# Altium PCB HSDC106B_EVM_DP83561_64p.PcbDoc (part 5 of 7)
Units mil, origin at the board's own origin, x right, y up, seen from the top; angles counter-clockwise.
Board outline 8750.24 x 6394.7 mil, 6 copper layers (Top Layer, GND1, SIG1, SIG2, GND2, Bottom Layer), stack 60.4 mil thick; 472 components, 324 nets, 1622 pads, 1086 vias.
Unrouted connection lines stored in the file: 1.
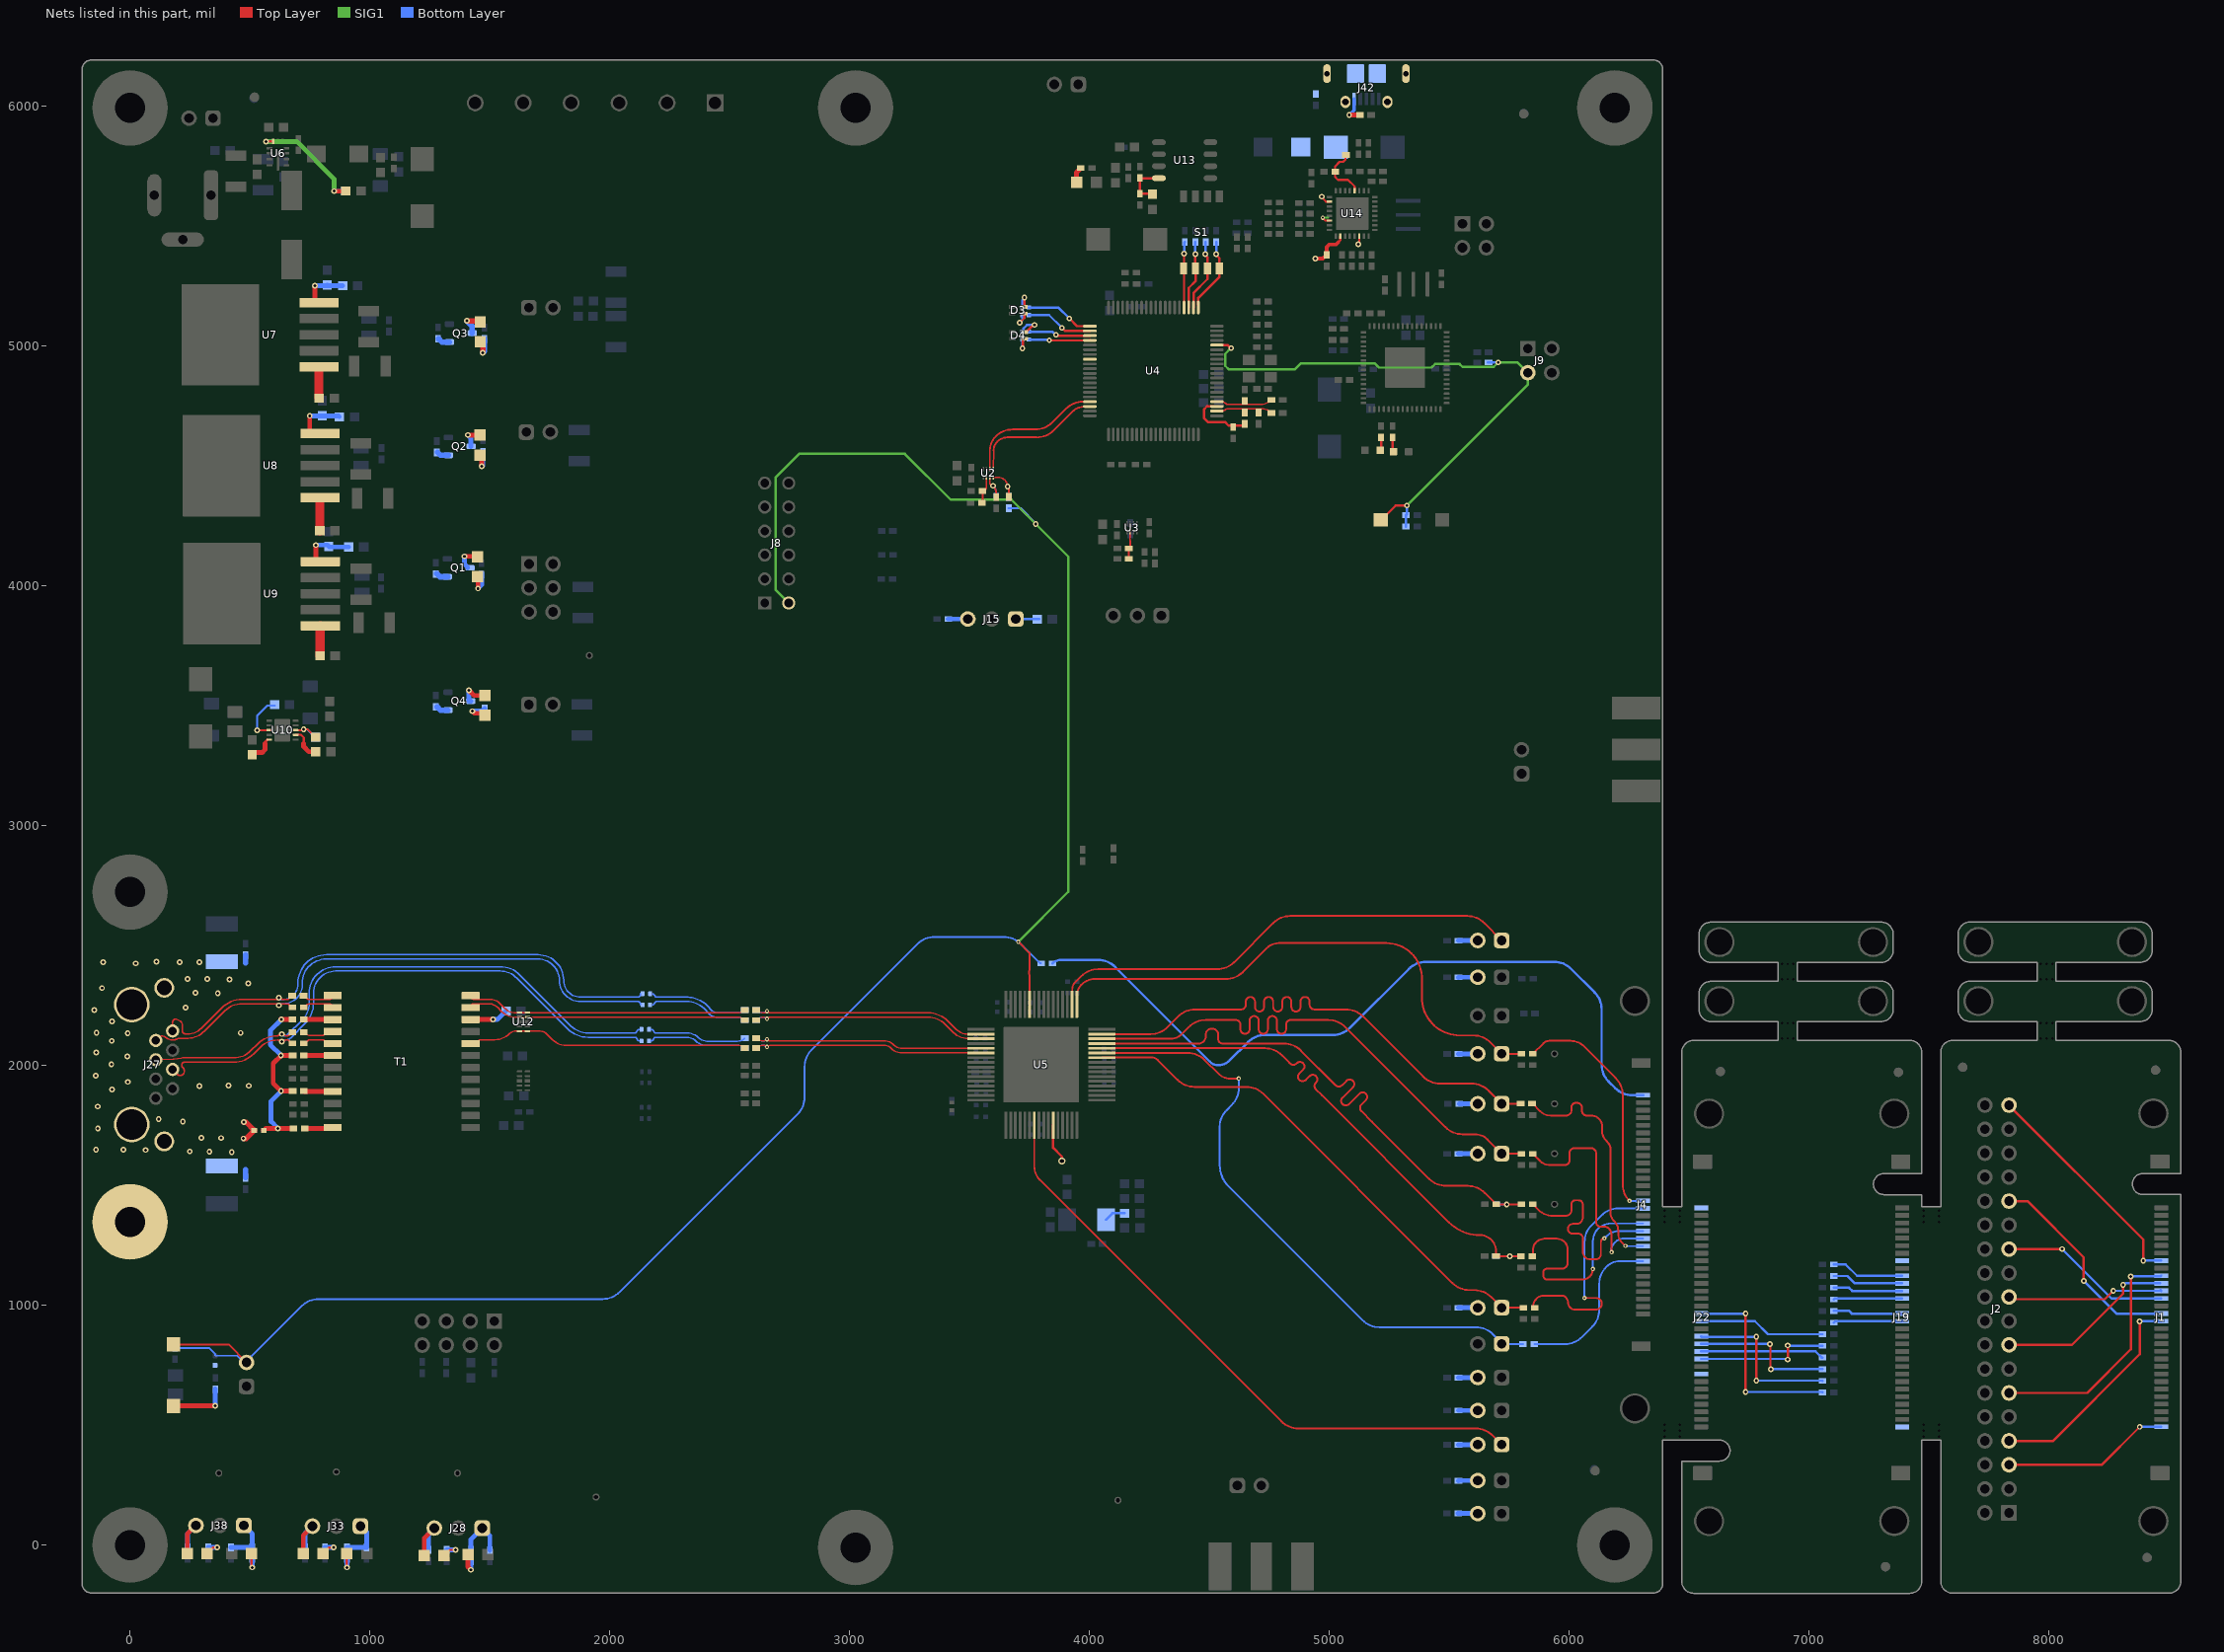
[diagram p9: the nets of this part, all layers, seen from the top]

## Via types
v1: diameter 24, hole 12, Top Layer to Bottom Layer, tented both sides, 903 vias
v2: diameter 24, hole 12, Top Layer to Bottom Layer, 65 vias
v3: diameter 18, hole 7.87, Top Layer to Bottom Layer, tented both sides, 53 vias
v4: diameter 22, hole 10, Top Layer to Bottom Layer, tented both sides, 43 vias
v5: diameter 19.68, hole 7.87, Top Layer to Bottom Layer, 21 vias
v6: diameter 22, hole 12, Top Layer to Bottom Layer, tented both sides, 1 vias

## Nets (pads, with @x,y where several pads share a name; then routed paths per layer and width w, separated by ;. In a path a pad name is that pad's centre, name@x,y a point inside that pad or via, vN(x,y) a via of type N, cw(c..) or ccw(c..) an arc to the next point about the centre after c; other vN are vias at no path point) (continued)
NetC79_2: C79.2 T1.10 | length 162.7
  Top Layer w20: T1.10@1419.86,2191.7 v1(1513.87,2191.7)
  Bottom Layer w20: v1(1513.87,2191.7) 1531.2,2191.7 C79.2@1567.5,2228
NetC82_1: C82.1 R107.1 R114.1 R117.1 R123.1 | length 819.7
  Top Layer w20: C82.1@557.28,1729.61 558.94,1729.61 566.94,1737.61 v1(616,1737.61) R107.1@680.98,1737.61 ; v1@628,2191 cw(c630.64,2188.36) v1(630.64,2192.09) R123.1@676.38,2192.09 ; R114.1@677.76,1893.61 v1(629.82,1893.61) 597,1926.43 597,2009.08 629.47,2041.56 v1(629.47,2042.64) R117.1@677.76,2041.7
  Bottom Layer w20: v1(616,1737.61) 616,1738.69 587.95,1766.74 587.95,1851.73 v1(629.82,1893.61) ; v1(629.47,2042.64) 585,2087.12 585,2146.45 v1(630.64,2192.09)
NetC94_1: C94.1 U10.7 | length 135.4
  Top Layer w9: U10.7@690.12,3378.7 U10.7@690.12,3379.01 712.68,3379.01 724,3367.7 724,3342.7
  Top Layer w20: 724,3342.7 724,3330.22 745.62,3308.61 C94.1@774.1,3308.61
NetC95_1: C95.1 R120.1 | length 416.9
  Bottom Layer w6: 2176.22,2299.61 cw(c2176.22,2290.1) 2182.94,2296.82 2188.2,2291.56 cw(c2186.34,2289.71) 2188.97,2289.71 ccw(c2191.59,2289.71) 2189.74,2287.85 ccw(c2196.37,2294.48) 2196.37,2285.11 2321.76,2285.11 cw(c2321.76,2167.19) 2332.56,2284.61 cw(c2321.76,2167.19) 2405.14,2250.57 2426.5,2229.21 ccw(c2449.46,2252.17) 2449.46,2219.7 2534.06,2219.7 ccw(c2534.06,2260.67) R120.1@2563.03,2231.7
NetC115_1: C115.1 R174.1 R176.2 U13.4 | length 199.7
  Top Layer w10: C115.1@4263.6,5633.61 4260.65,5636.56 R176.2@4210,5636.56 R174.1@4210,5701.42 4210.72,5700.7 U13.4@4289.72,5700.7
NetC116_1: C116.1 C117.2 D9.2 J42.1 | length 120.9
  Top Layer w20: v1(5082.98,5963.68) 5083.8,5964.5 5121.67,5964.5 C117.2@5127.42,5964.5
  Bottom Layer w15: v1(5082.98,5963.68) 5103.65,5984.35 5103.65,6029.3 J42.1@5103.65,6031.3
NetC126_1: C126.1 R198.1 U14.4 | length 234.5
  Top Layer w9: R198.1@5069.24,5797.7 5067.18,5795.64 5067.18,5778.65 5057.23,5768.7 5043,5768.7 5024.62,5750.32 C126.1@5024.62,5727.7 5024.62,5705.08 5036,5693.7 5078,5693.7 5105.25,5666.45 U14.4@5105.25,5647.99
NetD1_2: D1.2 R1.1 | length 54.9
  Top Layer w10: D1.2@5211.78,4565.7 ccw(c5201.59,4575.89) 5216,4575.89 R1.1@5216,4619.46
NetD2_2: D2.2 R2.1 | length 60.4
  Top Layer w10: R2.1@5264,4619.46 5264,4568.73 ccw(c5276.29,4568.73) D2.2@5267.6,4560.04
NetD3_1: D3.1 R70.1 | length 85.2
  Top Layer w10: v1(3708.6,5097.61) 3728.72,5117.73 D3.1@3728.72,5136.23
  Bottom Layer w10: v1(3708.6,5097.61) 3721.06,5110.06 R70.1@3721.06,5129.86 R70.1@3720.27,5129.86
NetD3_2: D3.2 R69.1 | length 84.2
  Top Layer w10: D3.2@3728.72,5163.79 v1(3728.72,5202.61)
  Bottom Layer w10: R69.1@3721.86,5162.38 R69.1@3721.06,5161.57 3721.06,5191.15 3728.72,5198.82 v1(3728.72,5202.61)
NetD4_1: D4.1 R72.1 | length 83.5
  Top Layer w10: v1(3720.6,4990.61) 3723.28,4993.28 3723.28,5028.2 3726.15,5031.08 D4.1@3730.17,5031.08
  Bottom Layer w10: v1(3720.6,4990.61) 3720.85,4990.86 3720.85,5026.89 R72.1@3721.11,5027.14
NetD4_2: D4.2 R71.1 | length 120
  Top Layer w10: D4.2@3730.17,5058.64 3736.07,5058.64 3763.36,5085.93 3767.92,5085.93 v1(3770.6,5088.61)
  Bottom Layer w10: R71.1@3721.11,5060.61 3721.9,5060.61 3725.17,5063.87 3725.17,5074.21 3739.57,5088.61 v1(3770.6,5088.61)
NetD5_1: D5.1 R102.1 | length 119.6
  Top Layer w20: D5.1@1448.6,4039.27 1450.6,4037.27 v1(1450.6,3989.61)
  Bottom Layer w20: v1(1450.6,3989.61) 1465.6,4004.61 R102.1@1465.6,4052.47
NetD5_2: D5.2 Q1.3 | length 110.1
  Top Layer w20: v1(1394.6,4123.61) 1448.6,4123.61 D5.2@1450.6,4125.61
  Bottom Layer w20: v1(1394.6,4123.61) 1394.6,4090.47 1407.56,4077.51 Q1.3@1407.56,4075.7
NetD6_1: D6.1 R103.1 | length 109.5
  Top Layer w20: D6.1@1458,4546.36 1466.6,4537.76 v1(1466.6,4499.61)
  Bottom Layer w20: v1@1469.6,4501.61 1471.6,4503.61 R103.1@1471.6,4559.98
NetD6_2: D6.2 Q2.3 | length 102.4
  Top Layer w20: v1@1409,4627.7 1410.34,4629.04 D6.2@1458,4629.04
  Bottom Layer w20: v1@1409,4629.7 1409,4628.55 1421.41,4616.14 1421.41,4583.91 1421.65,4583.68 Q2.3@1421.65,4582.1
  other v1: 1408,4629.7
NetD7_1: D7.1 R104.1 | length 110.4
  Top Layer w23: D7.1@1460,5018.36 1470.6,5007.76 v1(1470.6,4972.61)
  Bottom Layer w23: v1(1470.6,4972.61) 1477.6,4979.61 R104.1@1477.6,5029.98
NetD7_2: D7.2 Q3.3 | length 117.5
  Top Layer w23: v1(1405,5105.7) 1455.34,5105.7 D7.2@1460,5101.04
  Bottom Layer w23: v1@1404.54,5105.7 1404.73,5105.7 1405.19,5105.24 1405.19,5104.51 1425.21,5084.49 1425.21,5055.01 1425.52,5054.7 Q3.3@1426.24,5054.7
NetD8_1: D8.1 R105.1 | length 118.9
  Top Layer w20: v1(1426.4,3477.58) 1427.48,3477.58 1435.89,3469.17 1469.89,3469.17 D8.1@1478.6,3460.46
  Bottom Layer w20: v1(1426.4,3477.58) 1427.17,3478.34 1466.96,3478.34 1472.85,3484.24 1476.79,3484.24 1478.6,3486.05 R105.1@1478.6,3489.98
NetD8_2: D8.2 Q4.3 | length 126.7
  Top Layer w20: v1(1412.6,3564.8) 1434.26,3543.13 D8.2@1478.6,3543.13
  Bottom Layer w20: v1(1412.6,3564.8) 1412.6,3521.51 1414.41,3519.7 Q4.3@1420.24,3519.7
NetJ15_1: J15.1 R90.2 | length 95.6
  Bottom Layer w10: J15.1@3697.83,3867 3702.83,3862 R90.2@3791.33,3862
NetJ15_3: J15.3 R87.1 | length 88.4
  Bottom Layer w20: R87.1@3411.45,3862 J15.3@3492.83,3862 J15.3@3497.83,3867
NetJ28_1: J28.1 R149.2 R150.2 | length 215.6
  Bottom Layer w20: R149.2@1421.5,-19.77 1421.5,23.98 J28.1@1468.5,70.98 1500,39.48 R150.2@1500,-21.38
NetJ28_3: J28.3 LD1.2 R148.1 | length 233
  Top Layer w20: LD1.2@1226.66,-44 1226.66,29.14 J28.3@1268.5,70.98
  Bottom Layer w20: R148.1@1244.5,-19.77 1244.5,46.98 J28.3@1268.5,70.98
NetJ29_2: J29.2 R151.1 | length 80.8
  Bottom Layer w20: R151.1@5538.56,1631.93 5538.56,1632.34 J29.2@5618.99,1632.34
NetJ30_2: J30.2 R153.1 | length 80.8
  Bottom Layer w20: R153.1@5542.27,1840.17 5542.27,1840.58 J30.2@5618.99,1840.58 J30.2@5622.7,1840.58
NetJ31_2: J31.2 R156.1 | length 80.8
  Bottom Layer w20: R156.1@5538.56,2048.41 5538.56,2048.82 J31.2@5618.99,2048.82
NetJ32_2: J32.2 R160.1 | length 80.8
  Bottom Layer w20: R160.1@5538.56,989.59 5538.56,990 J32.2@5618.99,990
NetJ33_1: J33.1 R161.2 R162.2 | length 181.3
  Bottom Layer w20: R161.2@904,-9.77 R162.2@986,-9.77 986,53.48 J33.1@960.5,78.98
NetJ33_3: J33.3 LD3.2 R159.1 | length 231.2
  Top Layer w20: LD3.2@722.56,-34.95 722.56,41.04 J33.3@760.5,78.98
  Bottom Layer w20: R159.1@729.5,-9.77 729.5,47.98 J33.3@760.5,78.98
NetJ34_2: J34.2 R163.1 | length 80.8
  Bottom Layer w20: R163.1@5538.56,561.16 5538.56,561.57 J34.2@5618.99,561.57
NetJ35_2: J35.2 R164.1 | length 82.2
  Bottom Layer w20: R164.1@5537.22,132.61 5537.69,132.14 5618.53,132.14 J35.2@5618.99,131.67
NetJ36_2: J36.2 R165.1 | length 80.8
  Bottom Layer w20: R165.1@5538.56,268.61 5538.56,269.01 J36.2@5618.99,269.01
NetJ37_2: J37.2 R167.1 | length 80.8
  Bottom Layer w20: R167.1@5538.56,418.62 5538.56,419.03 J37.2@5618.99,419.03
NetJ38_1: J38.1 R170.2 R171.2 | length 195.3
  Bottom Layer w20: R171.2@420.5,-9.77 R170.2@509.5,-9.77 509.5,46.98 J38.1@474.5,81.98
NetJ38_3: J38.3 LD5.2 R168.1 | length 238.1
  Top Layer w20: LD5.2@238.66,-35 238.66,46.14 J38.3@274.5,81.98
  Bottom Layer w20: R168.1@239.5,-9.77 239.5,46.98 J38.3@274.5,81.98
NetJ39_2: J39.2 R169.1 | length 80.8
  Bottom Layer w20: R169.1@5538.56,698.36 5538.56,698.77 J39.2@5618.99,698.77
NetJ40_2: J40.2 R172.1 | length 80.8
  Bottom Layer w20: R172.1@5538.56,2521 5538.56,2521.41 J40.2@5618.99,2521.41
NetJ41_2: J41.2 R173.1 | length 80.8
  Bottom Layer w20: R173.1@5538.56,2367.87 5538.56,2368.28 J41.2@5618.99,2368.28
NetJ42_6: J42.6 J42.7 J42.8 J42.9 J42.10 J42.11 R177.1
NetLD1_1: LD1.1 R147.2 | length 93.7
  Top Layer w10: LD1.1@1309.34,-44 1333.56,-19.77 v1(1356.73,-19.77)
  Bottom Layer w20: R147.2@1320.5,-19.77 v1(1356.73,-19.77)
NetLD2_1: LD2.1 R149.1 | length 104.8
  Top Layer w20: LD2.1@1408.66,-40 1408.66,-90.41 v1(1421.5,-103.25)
  Bottom Layer w20: v1(1421.5,-103.25) R149.1@1421.5,-67.02
NetLD3_1: LD3.1 R157.2 | length 90.2
  Top Layer w10: LD3.1@805.23,-34.95 830.41,-9.77 v1(848.73,-9.77)
  Bottom Layer w20: R157.2@812.5,-9.77 v1(848.73,-9.77)
NetLD4_1: LD4.1 R161.1 | length 94.5
  Top Layer w10: v1(904,-93.25) 904.16,-93.09 LD4.1@904.16,-35
  Bottom Layer w20: v1(904,-93.25) R161.1@904,-57.02
NetLD5_1: LD5.1 R166.2 | length 88
  Top Layer w10: LD5.1@321.34,-35 346.53,-9.8 v1(362.72,-9.8)
  Bottom Layer w20: R166.2@326.49,-9.8 v1(362.72,-9.8)
NetLD6_1: LD6.1 R170.1 | length 95.8
  Top Layer w10: LD6.1@506.34,-35 506.34,-90.09 v1(509.5,-93.25)
  Bottom Layer w20: v1(509.5,-93.25) R170.1@509.5,-57.02
NetLD7_1: LD7.1 R175.1 | length 69.8
  Top Layer w20: LD7.1@3946.26,5682.7 3945.98,5682.98 3945.98,5724.61 3958.23,5736.86 3958.23,5740.8 3960.04,5742.61 R175.1@3963.98,5742.61
NetQ1_1: Q1.1 R108.2 | length 51.5
  Bottom Layer w23: R108.2@1278.57,4052.06 1292.35,4038.28 Q1.1@1324.33,4038.28
NetQ2_1: Q2.1 R109.2 | length 51.5
  Bottom Layer w23: R109.2@1281.4,4558.48 1295.18,4544.7 Q2.1@1327.16,4544.7
NetQ3_1: Q3.1 R110.2 | length 51.5
  Bottom Layer w23: R110.2@1286,5031.08 1299.78,5017.3 Q3.1@1331.76,5017.3
NetQ4_1: Q4.1 R111.2 | length 51.5
  Bottom Layer w23: R111.2@1280,3496.08 1293.78,3482.3 Q4.1@1325.76,3482.3
NetR21_1: R21.1 U7.1 | length 129.4
  Top Layer w38: R21.1@787.6,4784.11 U7.1@787.6,4913.53
NetR22_1: R22.1 U8.1 | length 138.1
  Top Layer w38: R22.1@791.1,4230.61 791.1,4367.16 791.79,4367.84 U8.1@792.42,4367.84
NetR24_1: R24.1 U9.1 | length 126.1
  Top Layer w38: R24.1@792.1,3708.61 792.1,3833.16 792.79,3833.84 U9.1@793.42,3833.84
NetR26_1: R26.1 U10.5 | length 109.9
  Top Layer w9.5: 562.4,3343.08 562.4,3348.89 U10.5@572.82,3359.3
  Top Layer w20: R26.1@508.6,3295.61 508.6,3296.59 517.3,3305.29 550.69,3305.29 562.4,3317.01 562.4,3343.08
NetR28_1: R28.1 R30.2 U10.8 | length 147
  Top Layer w9: U10.8@690.12,3398.7 721,3398.7 v1@726,3403.7 ; v1@734,3402.7 738.5,3402.7 R28.1@769.5,3371.7
  Bottom Layer w9: v1(724,3402.7) 738,3402.7 R30.2@771,3369.7
NetR35_2: R35.2 R36.1 U2.2 | length 117
  Top Layer w6: R35.2@3554.28,4396.32 ccw(c3554.28,4413.09) 3571.04,4413.09 U2.2@3571.04,4452.8
  Top Layer w8: R36.1@3551.22,4346.61 3554.28,4349.66 R35.2@3554.28,4396.32
NetR37_2: R37.2 R38.1 U3.2 | length 112.8
  Top Layer w6: 4169.71,4189.46 4169.61,4189.55 4169.61,4224.8 U3.2@4169.71,4224.89
  Top Layer w8: R38.1@4164.22,4113.61 R37.2@4164.22,4156.61 ccw(c4150.97,4169.86) 4169.71,4169.86 4169.71,4189.46
NetR78_2: R78.2 XTAL1.1 | length 89.5
  Bottom Layer w10: XTAL1.1@4068.68,1356.8 4095.68,1383.8 R78.2@4146.98,1383.8
NetR79_1: R79.1 S3.1 | length 244
  Top Layer w20: S3.1@181.41,580.65 v1(355.45,580.65)
  Bottom Layer w20: v1(355.45,580.65) R79.1@355.45,650.61
NetR92_1: R92.1 R94.2 U7.5 | length 204.4
  Top Layer w20: v1(770.6,5252.61) 770.6,5191.24 780.28,5181.56 U7.5@788.42,5181.56
  Bottom Layer w20: v1(770.6,5252.61) 819.91,5252.61 R94.2@822,5254.7 ; R94.2@818,5251.7 819,5252.7 R92.1@886.5,5252.7
NetR93_1: R93.1 R95.2 U6.7 | length 529.2
  Top Layer w10: v1(566.65,5853.8) v1(566.65,5853.8) 596.87,5853.76 U6.7@596.91,5853.72
  Top Layer w20: v1(850.6,5646.61) R93.1@900.1,5646.61
  SIG1 w20: v1(566.65,5853.8) 694.87,5853.8 850.6,5698.08 v1(850.6,5646.61)
  Bottom Layer w20: v1(850.6,5646.61) R95.2@900.1,5646.61
NetR96_1: R96.1 R98.2 U8.5 | length 236.6
  Top Layer w20: v1(749.02,4709.7) 749.02,4645.24 758.7,4635.56 U8.5@792.42,4635.56
  Bottom Layer w20: v1(749.02,4709.7) R98.2@801,4709.7 ; R98.2@801,4708.7 869.5,4708.7 R96.1@872.5,4705.7
NetR100_1: R100.1 R101.2 U9.5 | length 220.4
  Top Layer w20: v1(774.75,4170.7) 774.75,4111.24 784.44,4101.56 U9.5@793.42,4101.56
  Bottom Layer w20: v1@774.75,4168.7 776.75,4170.7 822.5,4170.7 R101.2@829,4164.2 ; R101.2@831,4162.7 R100.1@911.5,4162.7
NetR106_2: R106.2 U10.3 | length 200.7
  Top Layer w9: v1(530,3398.7) U10.3@579.88,3398.7
  Bottom Layer w9: v1(530,3398.7) 530,3458.7 573,3501.7 R106.2@603,3501.7
NetR107_2: R107.2 T1.24 | length 117.5
  Top Layer w20: R107.2@728.22,1737.61 834.78,1737.61 ccw(c834.78,1751.58) 841.66,1739.42 ccw(c834.78,1751.58) T1.24@844.66,1741.7
NetR114_2: R114.2 T1.21 | length 120.2
  Top Layer w20: R114.2@725,1893.61 ccw(c729.6,1898.21) 729.6,1891.7 T1.21@844.66,1891.7
NetR117_2: R117.2 T1.18 | length 119.7
  Top Layer w20: R117.2@725,2041.7 T1.18@844.66,2041.7
NetR123_2: R123.2 T1.15 | length 121.1
  Top Layer w20: R123.2@723.62,2192.09 ccw(c724.57,2193.04) 724.57,2191.7 T1.15@844.66,2191.7
NetU5_27: U5.27 VPP_TP1.1 | length 164.3
  Top Layer w10: U5.27@3848.77,1751.38 3848.77,1656.57 3885,1620.34 VPP_TP1.1@3885,1602.05
OC_N: R179.1 U14.10 U14.14 U14.18 U14.22 | length 325.8
  Top Layer w8: v1(4969,5623.7) 4969,5619.05 4985.33,5602.72 U14.10@5000.92,5602.72 ; v3(4972.6,5535.61) 4972.6,5533.78 4982.28,5524.09 5000.8,5524.09 U14.14@5000.92,5523.98 ; v1(5120.6,5425.61) 5120.6,5429.94 5124.6,5433.94 5124.6,5458.68 U14.22@5124.94,5459.02
  Top Layer w9: 5037.58,5433.32 5046.2,5441.94 U14.18@5046.2,5459.02 5045.77,5458.59 5045.77,5445.76
  Top Layer w15: v1@4938.67,5361.83 v1(4942.05,5365.2) 4972.88,5365.2 R179.1@4989,5381.32 4989,5412.7 5001,5424.7 5028.96,5424.7 5037.58,5433.32
  SIG1 w8: v3(4972.6,5535.61) 4996,5535.61
P1.0: R69.2 U4.21 | length 287
  Top Layer w10: v4(3916.54,5115.47) 3948.54,5083.47 U4.21@4001.71,5083.47
  Bottom Layer w10: R69.2@3747.04,5161.57 3870.44,5161.57 v4(3916.54,5115.47)
P1.1: R70.2 U4.22 | length 282
  Top Layer w10: v4(3885,5076.7) 3897.91,5063.79 U4.22@4001.71,5063.79
  Bottom Layer w10: R70.2@3747.04,5129.86 3831.84,5129.86 v4(3885,5076.7)
P1.2: R71.2 U4.23 | length 261.5
  Top Layer w10: v4(3861,5047.7) 3864.6,5044.1 U4.23@4001.71,5044.1
  Bottom Layer w10: R71.2@3747.09,5060.61 3844.85,5060.61 3857.75,5047.7 v4(3861,5047.7)
P1.3: R72.2 U4.24 | length 256.9
  Top Layer w10: v4(3832.68,5025.52) 3834.38,5023.83 4002.24,5023.83 U4.24@4002.52,5024.11
  Bottom Layer w10: R72.2@3747.09,5027.14 3747.9,5026.33 3831.87,5026.33 v4(3832.68,5025.52)
P1.7: U4.28
PWDN_LVL: R47.1 R55.2 U2.3 | length 142.7
  Top Layer w6: U2.3@3584.82,4452.8 3584.82,4431.76 ccw(c3598.6,4431.76) v1(3598.6,4417.98)
  Top Layer w8: v1(3598.6,4417.98) cw(c3567.58,4386.96) 3611.45,4386.96 R47.1@3611.45,4370.42
  Bottom Layer w8: v1(3598.6,4417.98) cw(c3567.58,4386.96) 3611.45,4386.96 R55.2@3611.45,4372.39
PWDN_MSP: U2.6 U4.37 | length 581.7
  Top Layer w6: U2.6@3584.82,4488.23 3584.82,4500.36 3584.72,4521.54 cw(c3651.71,4521.61) 3584.73,4521.97 3584.82,4538.94
  Top Layer w8: 3584.82,4538.94 3584.82,4565.48 cw(c3666.61,4565.48) 3608.78,4623.32 cw(c3679.49,4552.61) 3679.49,4652.61 3774.18,4652.61 ccw(c3774.18,4752.61) 3844.89,4681.9 3902.21,4739.22 cw(c3972.93,4668.51) 3972.93,4768.51 U4.37@4001.71,4768.51
RESET_LVL: R51.1 R57.2 U2.4 | length 178.3
  Top Layer w6: U2.4@3598.6,4452.8 3620.64,4452.8 cw(c3620.64,4414.61) v1(3658.83,4414.61)
  Top Layer w8: v1(3658.83,4414.61) cw(c3647.21,4402.99) 3663.64,4402.99 R51.1@3663.64,4371.42
  Bottom Layer w8: R57.2@3658.83,4376.61 R57.2@3663.64,4371.8 ; v1(3658.83,4414.61) cw(c3647.21,4402.99) 3663.64,4402.99 R57.2@3663.64,4371.8 ; R57.2@3663.64,4371.8 3663.82,4371.61 R57.2@3663.64,4371.42 R57.2@3663.64,4371.8
RESET_MSP: U2.5 U4.38 | length 554.4
  Top Layer w6: U2.5@3598.6,4488.23 3600.4,4565.48
  Top Layer w8: 3600.69,4565.48 cw(c3651.92,4565.48) 3615.7,4601.71 3616.6,4602.61 cw(c3657.64,4561.56) 3657.64,4619.61 3780.18,4619.61 ccw(c3780.18,4719.61) 3850.89,4648.9 3928.6,4726.61 cw(c3982.24,4672.96) 3982.24,4748.83 U4.38@4001.71,4748.83
RESET_N: C46.2 J8.2 J10.2 R34.1 R57.1 R80.2 S3.2 U5.59 | length 8953.9
  Top Layer w8: S3.2@181.41,836.56 411.16,836.56 J10.2@485.95,761.76 ; v3(3703.18,2515.89) 3749.74,2469.33 3749.74,2406.42 3749.14,2385.38 ccw(c3773,2384.7) 3749.14,2383.83 3749.48,2374.45 3750.35,2350.7 U5.59@3750.35,2255.08
  SIG1 w10: J8.2@2746,3929 2692,3983 2692,4453.61 2789.39,4551 3230,4551 3421,4360 3674.61,4360 v2(3776,4258.61) 3911.99,4122.61 3911.99,2724.7 v3(3703.18,2515.89)
  Bottom Layer w8: R80.2@187.29,822.42 329.26,822.42 354.5,797.19 354.5,793.25 ; 354.5,789.85 445.87,789.85 477.36,758.36 715.99,996.99 cw(c786.7,926.28) 786.7,1026.28 1970.52,1026.28 ccw(c1970.52,1126.28) 2041.24,1055.57 2783.36,1797.7 ccw(c2712.65,1868.41) 2812.65,1868.41 2812.65,1995.03 cw(c2912.65,1995.03) 2841.94,2065.74 3283.58,2507.38 cw(c3354.29,2436.67) 3354.29,2536.67 3642.51,2536.67 cw(c3642.51,2436.67) 3713.22,2507.38 3794.44,2426.17 R34.1@3798.37,2426.17 R34.1@3797.37,2427.17
  Bottom Layer w10: R57.1@3663.64,4324.17 3713.03,4324.17 3776,4261.2 v2(3776,4258.61)
RESETN_1: J1.60 J2.5 | length 701.2
  Top Layer w10: J2.5@7833.6,334.61 8220.5,334.61 v1(8379.21,493.31)
  Bottom Layer w10: v1(8379.21,493.31) J1.60@8469.11,493.31
RESETN_2: J22.60
RESETN_CS: J4.60 R34.2 | length 3201.8
  Bottom Layer w10: R34.2@3845.62,2426.17 cw(c3880.48,2391.31) 3880.48,2440.61 4036.18,2440.61 cw(c4036.18,2340.61) 4106.89,2411.32 4502.46,2015.75 ccw(c4536.6,2049.89) 4536.6,2001.61 ccw(c4536.6,2069.2) 4584.4,2021.41 4661.31,2098.32 cw(c4732.02,2027.61) 4732.02,2127.61 5015.18,2127.61 ccw(c5015.18,2227.61) 5085.89,2156.9 5332.31,2403.32 cw(c5403.02,2332.61) 5403.02,2432.61 5937.18,2432.61 cw(c5937.18,2332.61) 6007.89,2403.32 6106.12,2305.08 cw(c6035.41,2234.37) 6135.41,2234.37 6135.41,2003.96 ccw(c6235.41,2003.96) 6164.7,1933.25 6191.97,1905.98 ccw(c6262.68,1976.69) 6262.68,1876.69 J4.60@6308.86,1876.69
RESETN_LP: J19.60
RJ45_ERTH: C82.2 C108.2 C109.2 J27.9 J27.10 J27.11 J27.12 M8.1 R145.1 R146.1 | length 185.9
  Top Layer w22: v1(473,1695.64) 473.38,1696.02 484.67,1696.02 517.91,1729.26 C82.2@517.91,1729.61 517.91,1729.95 484.64,1763.22 474.98,1763.22 v1(474.6,1763.61)
  Bottom Layer w22: R145.1@481.17,1531.62 481.17,1566.95 ; 482,2426.64 R146.1@482,2460.38
  other v1: 424,1638.64 331,1640.64 249,1641.64 65,1647.64 -142,1649.64 -28,1649.64 380,1697.64 298,1698.64 -134,1738 220,1766 119.33,1776 -135,1829 -75,1899.64 289,1914.6 494.7,1915.4 410.98,1916.47 -9,1931.64 -143,1957.64 -78,2005.64 -12,2037.64 -141,2054.64 -76,2102.64 -10,2134.64 461,2136 -140,2136.64 -75,2184.64 -149,2231 230.92,2241.27 366,2301.64 273,2303.64 -117,2323 493,2342.64 415,2358.64 322,2360.64 240,2361.64 24,2426 289,2430.64 -112.1,2431.49 207,2431.64 110,2433.64
RST/SBWTDIO: C25.1 J9.3 R10.2 R75.2 S2.2 U4.76 | length 2498.8
  Top Layer w10: U4.76@4531.24,5004.73 4575.23,5004.73 4587.35,4992.61 v4(4590.6,4992.61) ; S2.2@5215.05,4275.7 5217.02,4275.7 5276.3,4334.98 v4(5323,4334.98)
  SIG1 w10: v4(4590.6,4992.61) 4566.41,4968.42 4566.41,4917.72 4581.39,4902.73 4856.06,4902.73 4882.03,4928.7 5189,4928.7 5207,4910.7 5425.69,4910.7 5440.72,4925.72 5543.15,4925.72 5555.18,4913.7 5686,4913.7 v4(5704,4931.7) 5785.5,4931.7 J9.3@5827.6,4889.61 5826.89,4888.9 5826.89,4838.88 v4(5323,4334.98)
  Bottom Layer w10: C25.1@5319.38,4247.61 R75.2@5319.38,4295.61 5323,4299.23 v4(5323,4334.98) ; R10.2@5661.62,4932.7 5703,4932.7 v4(5704,4931.7)
RX_CLK: J32.1 R18.1 U5.42 | length 2162.6
  Top Layer w8: U5.42@4052.23,2033.57 4259.41,2033.57 cw(c4259.41,1998.04) 4284.52,2023.18 ; 4284.53,2023.17 4367.29,1940.41 ccw(c4438,2011.13) 4438,1911.13 4653.96,1911.13 cw(c4653.96,1811.13) 4724.67,1881.84 5513.71,1092.79 ccw(c5584.42,1163.5) 5584.42,1063.5 5604.07,1063.5 cw(c5604.07,963.5) 5674.78,1034.21 J32.1@5718.99,990 R18.1@5801.34,990
RX_CLK_1: J1.30 J2.27 | length 887.2
  Top Layer w10: J2.27@7833.6,1434.61 7910.6,1434.61 8145.6,1199.61 v1(8145.6,1101.61)
  Bottom Layer w10: v1(8145.6,1101.61) 8281.6,965.61 8468.97,965.61 J1.30@8469.11,965.75
RX_CLK_2: J22.30 R201.1 | length 528.9
  Bottom Layer w10: J22.30@6550.68,933.86 6774.35,933.86 6828.87,879.33 R201.1@7056.98,879.33
RX_CLK_LP: J19.30 R202.2 | length 288.8
  Bottom Layer w10: R202.2@7104.22,976.42 7167.72,976.42 7178.49,965.66 J19.30@7388.6,965.66
RX_CTRL: J31.1 R19.1 U5.49 | length 2264.7
  Top Layer w8: U5.49@3947.2,2255.08 3947.2,2290.6 cw(c4013.1,2290.6) 3966.5,2337.2 ; 3966.53,2337.23 cw(c4023.08,2280.62) 4023.08,2360.64 4568.9,2360.64 ccw(c4568.9,2460.64) 4639.61,2389.93 4739.77,2490.08 cw(c4788.98,2440.87) 4788.98,2510.46 5239.07,2510.46 cw(c5239.07,2363.54) 5386,2363.54 5386,2283.55 ccw(c5544.05,2283.55) 5544.05,2125.51 5600.88,2125.51 cw(c5600.88,2025.51) 5671.6,2096.22 J31.1@5718.99,2048.82 R19.1@5801.34,2048.82
RX_CTRL_1: J1.32 J2.7 | length 922.7
  Top Layer w10: J2.7@7833.6,434.61 8017.6,434.61 8379.08,796.09 v1(8379.08,933.09)
  Bottom Layer w10: v1(8379.08,933.09) 8380.24,934.25 J1.32@8469.11,934.25
RX_CTRL_2: J22.32 R130.1 | length 834.2
  Top Layer w10: v1(6735.6,638.61) v1(6735.6,965.61)
  Bottom Layer w10: J22.32@6550.68,965.35 6550.81,965.48 6735.47,965.48 v1(6735.6,965.61) ; v1(6735.6,638.61) 7054.98,638.61 R130.1@7056.98,636.61
RX_CTRL_LP: J19.32 R207.2 | length 287
  Bottom Layer w10: R207.2@7104.22,927.88 7109.95,933.61 7388.04,933.61 J19.32@7388.6,934.17
RX_D0: R17.1 R152.1 R154.2 U5.44 | length 2307.9
  Top Layer w8: U5.44@4051.41,2072.12 4731.45,2072.12 cw(c4731.45,1972.12) 4802.16,2042.84 4833.5,2011.5 4836.33,2008.67 ccw(c4849.76,2022.11) 4863.2,2008.67 4863.98,2009.45 cw(c4877.42,1996.02) 4890.85,2009.45 cw(c4877.42,1996.02) 4890.85,1982.58 4875.13,1966.86 ccw(c4888.56,1953.42) 4875.13,1939.99 ccw(c4888.56,1953.42) 4902,1939.99 4917.72,1955.71 cw(c4931.16,1942.28) 4944.59,1955.71 cw(c4931.16,1942.28) 4944.59,1928.84 4943.81,1928.06 ccw(c4957.24,1914.63) 4943.81,1901.19 4968.74,1876.26 5498.71,1346.29 ccw(c5627.95,1475.53) 5627.95,1292.76 cw(c5627.95,1225.61) 5695.1,1225.61 R152.1@5695.1,1205.42 5751.99,1205.42 5796.12,1205.42 cw(c5796.12,1201.38) R17.1@5798.98,1204.24
  Bottom Layer w8: R154.2@5695.1,1205.42 5695.69,1204.83 5751.4,1204.83 v1(5751.99,1204.24)
RX_D0_1: J1.26 J2.23 | length 721
  Top Layer w10: J2.23@7833.6,1234.61 v1(8055.79,1234.61)
  Bottom Layer w10: v1(8055.79,1234.61) 8261.79,1028.61 8430.69,1028.61 8430.83,1028.46 8468.83,1028.46 J1.26@8469.11,1028.74
RX_D0_2: J22.26 R132.1 | length 690.3
  Top Layer w10: v1(6780.6,685.88) v1(6780.6,868.61)
  Bottom Layer w10: J22.26@6550.68,870.87 6552.94,868.61 v1(6780.6,868.61) ; v1(6780.6,685.88) 7056.25,685.88 R132.1@7056.98,685.15
RX_D0_LP: J19.26 R206.2 | length 285.9
  Bottom Layer w10: R206.2@7104.22,1024.97 7107.9,1028.65 J19.26@7388.6,1028.65
RX_D1: R16.1 R155.1 R158.2 U5.45 | length 2402.1
  Top Layer w8: U5.45@4051.41,2091.81 4455.62,2091.81 ccw(c4455.62,2120.99) 4484.8,2120.99 4484.8,2128.28 cw(c4510.59,2128.28) 4510.59,2154.08 cw(c4510.59,2127.67) 4537,2127.67 4537,2110.43 ccw(c4555.62,2110.43) 4555.62,2091.81 4810.88,2091.81 cw(c4810.88,1991.81) 4881.59,2062.52 5023.43,1920.68 5026.26,1917.85 ccw(c5039.69,1931.29) 5053.13,1917.85 5071.59,1936.32 cw(c5085.03,1922.89) 5098.46,1936.32 cw(c5085.03,1922.89) 5098.46,1909.45 5055.09,1866.08 ccw(c5068.52,1852.64) 5055.09,1839.21 ccw(c5068.52,1852.64) 5081.96,1839.21 5125.33,1882.58 cw(c5138.77,1869.15) 5152.2,1882.58 cw(c5138.77,1869.15) 5152.2,1855.71 5133.74,1837.24 ccw(c5147.17,1823.81) 5133.74,1810.37 5177.86,1766.25 5416.77,1527.34 ccw(c5487.48,1598.05) 5487.48,1498.05 5577.38,1498.05 cw(c5577.38,1398.05) 5648.09,1468.76 R155.1@5695.63,1421.22 v1(5739.6,1421.22) R16.1@5801.34,1421.22
  Bottom Layer w8: R158.2@5695.63,1421.22 v1(5739.6,1421.22)
RX_D1_1: J1.24 J2.19 | length 656.5
  Top Layer w10: J2.19@7833.6,1034.61 7842.6,1025.61 8233.6,1025.61 v1(8268.6,1060.61)
  Bottom Layer w10: v1(8268.6,1060.61) 8462.55,1060.61 8465.65,1063.7 J1.24@8469.11,1060.24
RX_D1_2: J22.24 R134.1 | length 608.7
  Top Layer w10: v1(6836.6,838.61) 6839.1,836.11 6839.1,736.11 v1(6841.6,733.61)
  Bottom Layer w10: J22.24@6550.68,839.37 6551.44,838.61 v1(6836.6,838.61) ; v1(6841.6,733.61) 6841.69,733.7 R134.1@7056.98,733.7
RX_D1_LP: J19.24 R205.2 | length 289.9
  Bottom Layer w10: R205.2@7104.22,1073.51 7166.69,1073.51 7180.06,1060.15 J19.24@7388.6,1060.15
RX_D2: J29.1 R15.1 U5.46 | length 2307
  Top Layer w8: U5.46@4051.41,2111.49 4340.25,2111.49 ccw(c4340.25,2171.97) 4383.01,2129.21 4414.22,2160.41 cw(c4484.93,2089.7) 4484.93,2189.7 4568.6,2189.7 4610.6,2189.7 cw(c4610.6,2170.7) 4629.6,2170.7 4629.6,2151.33 ccw(c4648.6,2151.33) 4667.6,2151.33 4667.6,2187.23 cw(c4686.6,2187.23) 4705.6,2187.23 4705.6,2151.33 ccw(c4724.6,2151.33) 4743.6,2151.33 4743.6,2187.23 cw(c4762.6,2187.23) 4781.6,2187.23 4781.6,2151.33 ccw(c4800.6,2151.33) 4819.6,2151.33 4819.6,2170.7 cw(c4838.6,2170.7) 4838.6,2189.7 4878.79,2189.7 4995.91,2189.7 cw(c4995.91,2089.7) 5066.62,2160.41 5484.22,1742.81 ccw(c5554.93,1813.52) 5554.93,1713.52 5607.14,1713.52 5607.19,1713.52 cw(c5607.19,1639.62) 5659.39,1691.94 5659.46,1691.87 J29.1@5718.99,1632.34 R15.1@5801.34,1632.34
RX_D2_1: J1.22 J2.15 | length 759.1
  Top Layer w10: J2.15@7833.6,834.61 8095.6,834.61 8309.47,1048.48 v1(8309.47,1085.48)
  Bottom Layer w10: v1(8309.47,1085.48) 8313.26,1085.48 8320.39,1092.61 J1.22@8464.17,1092.61
RX_D2_2: J22.22 R135.1 | length 516.9
  Bottom Layer w10: J22.22@6550.68,807.87 7027.41,807.87 7053.04,782.24 R135.1@7056.98,782.24
RX_D2_LP: J19.22 R204.2 | length 297
  Bottom Layer w10: R204.2@7104.22,1122.06 7160.15,1122.06 7190.56,1091.65 J19.22@7388.6,1091.65
RX_D3: J30.1 R14.1 U5.47 | length 2271.1
  Top Layer w8: U5.47@4051.41,2131.18 4255.37,2131.18 ccw(c4255.37,2231.18) 4326.08,2160.47 4370.62,2205.01 cw(c4441.33,2134.3) 4441.33,2234.3 4628.92,2234.3 4632.92,2234.3 ccw(c4632.92,2253.3) 4651.92,2253.3 4651.92,2266.87 cw(c4670.92,2266.87) 4689.92,2266.87 4689.92,2244.16 ccw(c4708.92,2244.16) 4727.92,2244.16 4727.92,2266.87 cw(c4746.92,2266.87) 4765.92,2266.87 4765.92,2244.16 ccw(c4784.92,2244.16) 4803.92,2244.16 4803.92,2266.87 cw(c4822.92,2266.87) 4841.92,2266.87 4841.92,2244.16 ccw(c4860.92,2244.16) 4879.92,2244.16 4879.92,2266.87 cw(c4898.92,2266.87) 4917.92,2266.87 4917.92,2253.3 ccw(c4936.92,2253.3) 4936.92,2234.3 4974.63,2234.3 5068.98,2234.3 cw(c5068.98,2134.3) 5139.69,2205.01 5390.71,1953.99 ccw(c5461.42,2024.7) 5461.42,1924.7 5593.45,1924.7 cw(c5593.45,1824.7) 5664.16,1895.41 J30.1@5718.99,1840.58 R14.1@5801.34,1840.58
RX_D3_1: J1.20 J2.11 | length 1016.3
  Top Layer w10: J2.11@7833.6,634.61 8159.6,634.61 8341.6,816.61 v1(8341.6,1120.67)
  Bottom Layer w10: v1(8341.6,1120.67) 8465.79,1120.67 8468.73,1123.61 J1.20@8469.11,1123.23
RX_D3_2: J22.20 R136.1 | length 567.4
  Top Layer w10: v1(6911.6,773.61) v1(6911.6,832.75)
  Bottom Layer w10: J22.20@6550.68,776.38 6908.83,776.38 v1(6911.6,773.61) ; v1(6911.6,832.75) 6912.58,831.77 7056,831.77 R136.1@7056.98,830.79
RX_D3_LP: J19.20 R203.2 | length 304
  Bottom Layer w10: R203.2@7104.22,1170.61 7152.6,1170.61 7200.06,1123.14 J19.20@7388.6,1123.14
RX_ER: J5.1 R13.1 U5.43 | length 2582.9
  Top Layer w8: U5.43@4051.41,2052.44 4409.93,2052.45 cw(c4409.93,1952.45) 4480.64,2023.16 4537.4,1966.4 ; 4537.43,1966.37 ccw(c4587.6,2016.59) 4587.6,1945.61 v3(4622.6,1945.61)
  Bottom Layer w8: v3(4622.6,1945.61) 4622.6,1906.03 cw(c4522.6,1906.03) 4593.31,1835.32 4571.6,1813.61 ccw(c4640.03,1745.17) 4543.25,1745.17 4543.25,1583.72 4543.25,1583.67 ccw(c4665.09,1583.66) 4578.94,1497.51 4578.99,1497.46 5138.47,937.98 ccw(c5209.18,1008.69) 5209.18,908.69 5611.56,908.69 cw(c5611.56,808.69) 5682.27,879.4 5723.06,838.61 R13.1@5807.35,838.61
RX_ER_1: J1.16 J2.35 | length 955.6
  Top Layer w10: J2.35@7833.6,1834.61 8394,1274.2 v1(8394,1186.22)
  Bottom Layer w10: v1(8394,1186.22) J1.16@8469.11,1186.22
RX_ER_2: J22.16
RX_ER_CS: J4.16 R13.2 | length 692.7
  Bottom Layer w8: R13.2@5854.6,838.61 5982.89,838.61 ccw(c5982.89,938.61) 6053.6,867.9 6096.36,910.66 ccw(c6025.65,981.37) 6125.65,981.37 6125.65,1089.5 cw(c6225.65,1089.5) 6154.94,1160.21 cw(c6211.84,1103.32) 6211.84,1183.78 J4.16@6308.86,1183.78
RX_ER_LP: J19.16
RXCLK_CS: J4.30 R18.2 | length 1002.2
  Top Layer w8: R18.2@5848.59,990 cw(c5903.22,990) 5864.59,1028.63 cw(c5892.03,1001.19) 5892.03,1040 5972.81,1040 cw(c5972.81,1025) 5983.42,1035.61 5986.75,1032.27 cw(c5966.1,1011.62) 5995.31,1011.62 ccw(c6024.97,1011.62) 6024.97,981.95 6110.66,981.95 ccw(c6110.66,1007.24) 6135.95,1007.24 ccw(c6112.59,1007.24) 6130.5,1022.24 ccw(c6112.59,1007.24) 6112.59,1030.61 v3(6064.14,1030.61)
  Bottom Layer w8: v3(6064.14,1030.61) 6064.14,1263.17 cw(c6164.14,1263.17) 6093.43,1333.88 6134.51,1374.96 cw(c6205.22,1304.25) 6205.22,1404.25 J4.30@6308.86,1404.25
RXCTRL_CS: J4.32 R19.2 | length 1011.8
  Top Layer w8: R19.2@5848.59,2048.82 5892.8,2093.03 cw(c5916.72,2069.11) 5916.72,2102.94 6005.42,2102.94 cw(c6005.42,2022.35) 6062.37,2079.38 cw(c6005.42,2022.35) 6062.41,2079.34 6193.72,1948.03 cw(c6123.01,1877.32) 6223.01,1877.32 6223.01,1504.78 ccw(c6320.63,1504.78) v3(6251.6,1435.75)
  Bottom Layer w8: v3(6251.6,1435.75) J4.32@6308.86,1435.75
RXD0_CS: J4.26 R17.2 | length 1026
  Top Layer w8: R17.2@5848.59,1204.24 5848.59,1229.1 cw(c5897.23,1229.1) 5897.23,1277.75 5948.75,1277.75 cw(c5948.75,1232.43) 5994.06,1232.43 5994.06,1178.06 cw(c5968.6,1178.06) 5968.6,1152.61 5906.8,1152.61 ccw(c5906.8,1138.61) 5892.8,1138.61 5892.8,1123.1 ccw(c5908.6,1123.1) 5908.6,1107.3 6054.7,1107.3 ccw(c6054.7,1151.77) v3(6099.17,1151.77)
  Bottom Layer w8: v3(6099.17,1151.77) 6099.17,1267.63 cw(c6172.8,1267.63) 6124.78,1323.44 cw(c6172.8,1267.63) 6172.8,1341.26 J4.26@6308.86,1341.26
RXD1_CS: J4.24 R16.2 | length 918.4
  Top Layer w8: R16.2@5848.59,1421.22 5870.24,1399.57 ccw(c5933.34,1462.66) 5933.34,1373.43 5985.24,1373.43 ccw(c5985.24,1398.14) 6009.94,1398.14 6009.94,1422.27 cw(c6025.83,1422.27) 6025.83,1438.16 6038.78,1438.16 cw(c6038.78,1419.91) 6057.02,1419.91 6057.02,1366.28 cw(c6030.37,1366.28) 6030.37,1339.63 6015.57,1339.63 ccw(c6015.57,1318.7) 5994.64,1318.7 ccw(c6014.64,1318.7) 6014.64,1298.7 6038.18,1298.7 cw(c6038.18,1279.86) 6057.02,1279.86 6057.02,1222.19 ccw(c6087.62,1222.19) 6087.62,1191.59 6111.16,1191.59 ccw(c6111.16,1212.78) 6132.34,1212.78 6132.34,1264.49 cw(c6146.85,1264.49) v3(6146.85,1279)
  Bottom Layer w8: v3(6146.85,1279) 6156.02,1288.17 cw(c6208.15,1236.04) 6208.15,1309.76 J4.24@6308.86,1309.76
RXD2_CS: J4.22 R15.2 | length 970.7
  Top Layer w8: R15.2@5848.59,1632.34 5880.22,1600.7 ccw(c5916.12,1636.61) 5916.12,1585.83 5983.96,1585.83 ccw(c5983.96,1603) 6001.13,1603 6001.13,1633.68 cw(c6023.17,1633.68) 6023.17,1655.72 6090.28,1655.72 cw(c6090.28,1633.09) 6112.91,1633.09 6112.91,1345.53 ccw(c6130.53,1345.53) 6130.53,1327.92 6148.6,1327.92 cw(c6148.6,1305.17) 6164.68,1321.26 cw(c6135.27,1291.84) 6176.87,1291.84 v3(6176.87,1221.34)
  Bottom Layer w8: v3(6176.87,1221.34) cw(c6176.87,1223.61) 6174.6,1223.61 cw(c6229.26,1223.61) 6229.26,1278.27 J4.22@6308.86,1278.27
RXD3_CS: J4.20 R14.2 | length 1005.8
  Top Layer w8: R14.2@5848.59,1840.58 5879.95,1809.22 ccw(c5922.46,1851.73) 5922.46,1791.61 5987.52,1791.61 ccw(c5987.52,1813.96) 6009.87,1813.96 6009.87,1826.64 cw(c6027.23,1826.64) 6027.23,1844 6033.36,1844 cw(c6033.36,1823.74) 6053.62,1823.74 6053.62,1810.91 ccw(c6072.92,1810.91) 6072.92,1791.61 6091.18,1791.61 cw(c6091.18,1744.93) 6137.87,1744.93 6137.87,1724.41 ccw(c6187.34,1724.41) 6138.24,1718.38 ccw(c6187.34,1724.41) 6152.36,1689.43 ccw(c6216.75,1734.99) 6160.97,1679.21 ; 6160.99,1679.19 cw(c6132.9,1651.14) 6172.6,1651.14 6172.6,1386.09 ccw(c6220.4,1386.09) 6186.6,1352.29 6189.26,1349.63 cw(c6152.24,1312.61) 6204.6,1312.61 6204.6,1298.7 ccw(c6255.52,1298.7) 6219.51,1262.7 v3(6234.6,1247.61)
  Bottom Layer w8: v3(6234.6,1247.61) ccw(c6235.43,1247.61) 6235.43,1246.77 J4.20@6308.86,1246.77
SMI_DISABLE: J40.1 U5.50 | length 2012.7
  Top Layer w8: U5.50@3928.42,2256 3928.42,2319.7 cw(c3965.64,2319.7) 3939.32,2346.02 3965.62,2372.32 cw(c4036.33,2301.61) 4036.33,2401.61 4532.18,2401.61 ccw(c4532.18,2501.61) 4602.9,2430.9 4766.32,2594.32 cw(c4837.03,2523.61) 4837.03,2623.61 5575.38,2623.61 cw(c5575.38,2523.61) 5646.09,2594.32 J40.1@5718.99,2521.41
SUPPLYMODESEL: J37.1 U5.23 | length 2609
  Top Layer w8: U5.23@3770.03,1751.38 3770.03,1579.6 ccw(c3850.9,1579.6) 3793.72,1522.42 4800.48,515.65 ccw(c4871.19,586.36) 4871.19,486.36 5610.24,486.36 cw(c5610.24,386.36) 5680.95,457.07 J37.1@5718.99,419.03
SW1: R65.1 S1.4 U4.1 | length 305.1
  Top Layer w10: U4.1@4453.48,5172.05 4453.48,5201.49 4542,5290.01 S1.4@4542,5324.7 4542,5366.42 4528.6,5379.82 v1(4528.6,5383.61)
  Bottom Layer w10: v1(4528.6,5383.61) R65.1@4528.6,5434.98
SW2: R64.1 S1.3 U4.2 | length 302
  Top Layer w10: U4.2@4433.8,5161.23 4433.8,5221.8 4492,5280.01 S1.3@4492,5324.7 4492,5371.16 4483.34,5379.82 v1(4483.34,5383.61)
  Bottom Layer w10: v1(4483.34,5383.61) 4483.97,5384.24 4483.97,5434.35 R64.1@4484.6,5434.98
SW3: R63.1 S1.2 U4.3 | length 285.5
  Top Layer w10: U4.3@4414.11,5161.23 4414.11,5243.12 4442,5271.01 S1.2@4442,5324.7 4441.6,5325.1 v1(4441.6,5383.61)
  Bottom Layer w10: v1(4441.6,5383.61) R63.1@4441.6,5434.98
SW4: R62.1 S1.1 U4.4 | length 277.1
  Top Layer w10: U4.4@4394.43,5161.23 4394.43,5322.27 S1.1@4392,5324.7 4394.6,5327.3 v1(4394.6,5385.61)
  Bottom Layer w10: v1(4394.6,5385.61) 4396.1,5387.11 4396.1,5433.48 R62.1@4397.6,5434.98
TARGET_D_N: C123.1 R180.1 U4.64 | length 240.4
  Top Layer w6: U4.64@4531.24,4768.51 4547.67,4768.51 cw(c4547.67,4732.03) 4573.46,4757.83 4713.55,4757.83 ccw(c4713.55,4823.21) C123.1@4759.78,4776.98 ; C123.1@4759.78,4775.98 C123.1@4762.5,4778.7
TARGET_D_P: C122.1 R73.2 R183.1 U4.62 | length 240.6
  Top Layer w6: U4.62@4531.24,4729.14 4547.67,4729.14 ccw(c4547.67,4765.62) 4573.46,4739.83 4718.6,4739.83 cw(c4718.6,4692.07) 4752.36,4725.84 C122.1@4761.5,4716.7
TARGET_PUR: R73.1 R74.1 U4.63 | length 287.8
  Top Layer w10: U4.63@4535.36,4749.4 4490.25,4749.4 4477.12,4736.27 4477.12,4700.27 4493.74,4683.65 4564.74,4683.65 4579.74,4668.65 4599.6,4668.65 R73.1@4652.12,4668.65
TD_A_cap_N: C97.1 R124.1 | length 416.9
  Bottom Layer w6: 2176.22,2252.61 ccw(c2176.22,2262.11) 2182.94,2255.39 2188.2,2260.65 ccw(c2186.34,2262.5) 2188.97,2262.5 cw(c2191.59,2262.5) 2189.74,2264.36 cw(c2196.37,2257.73) 2193.36,2266.61 cw(c2196.37,2257.73) 2196.37,2267.11 2321.73,2267.11 cw(c2321.73,2167.11) 2331.67,2266.61 cw(c2321.73,2167.11) 2392.44,2237.82 2413.77,2216.48 ; 2413.78,2216.48 ccw(c2449.46,2252.17) 2449.46,2201.7 2534.06,2201.7 cw(c2534.06,2160.73) R124.1@2563.03,2189.7
TD_A_mag_N: R125.2 T1.14 | length 149.8
  Top Layer w6: R125.2@723.62,2243 ccw(c723.62,2252.51) 730.34,2245.78 737.49,2252.93 cw(c749,2241.43) 749,2257.7 828.66,2257.7 cw(c828.66,2241.7) T1.14@844.66,2241.7 T1.14@830.58,2241.7 ; T1.14@810.16,2253.66 T1.14@810.16,2254.18
TD_A_mag_P: R128.2 T1.13 | length 135.6
  Top Layer w6: R128.2@723.22,2290.61 cw(c723.22,2281.1) 729.94,2287.82 737.16,2280.6 ccw(c749,2292.45) 749,2275.7 828.66,2275.7 ccw(c828.66,2291.7) T1.13@844.66,2291.7
TD_A_N: R122.2 R124.2 U5.3 | length 1025.2
  Top Layer w6: R122.2@2612.07,2189.71 cw(c2640.17,2161.58) 2640.17,2201.35 2641.88,2201.35 cw(c2641.88,2179.08) v3@2656.8,2195.61 ; U5.3@3547.71,2111.49 ccw(c3545.67,2109.46) 3545.67,2112.34 3494.75,2112.34 cw(c3494.75,2200.56) 3432.37,2138.18 3398.13,2172.41 ccw(c3327.42,2101.7) 3327.42,2201.7 2672.74,2201.7 ccw(c2672.74,2177.8) v3@2656.8,2195.61 ; v3(2655.84,2194.7) cw(c2672.59,2177.95) v3@2656.8,2195.6 ; v3(2655.84,2194.7) cw(c2672.74,2177.8) v3@2656.8,2195.6 ; v3(2655.84,2194.7) 2655.89,2194.7 v3@2656.8,2195.6
  Bottom Layer w6: R124.2@2610.28,2189.7 cw(c2638.39,2161.58) 2638.39,2201.35 2640.1,2201.35 cw(c2640.1,2179.08) v3@2655.84,2194.83
TD_A_P: R119.2 R120.2 U5.2 | length 1058.8
  Top Layer w6: R119.2@2612.07,2231.69 ccw(c2640.17,2259.82) 2640.17,2220.05 2641.88,2220.05 ccw(c2641.88,2242.32) v3@2656.73,2225.73 ; v3(2655.84,2226.57) ccw(c2672.59,2243.32) v3@2656.73,2225.73 ; U5.2@3511.4,2131.18 U5.2@3547.71,2131.18 cw(c3545.67,2133.21) 3545.67,2130.34 3494.88,2130.34 cw(c3494.88,2200.88) 3445,2151 3410.79,2185.21 ccw(c3327.52,2101.94) 3327.52,2219.7 2671.29,2219.7 cw(c2671.29,2240.29) v3@2656.73,2225.73
  Bottom Layer w6: R120.2@2610.28,2231.7 ccw(c2638.39,2259.82) 2638.39,2220.05 2640.1,2220.05 ccw(c2640.1,2242.32) v3(2655.84,2226.57)
TD_A_RJ_N: C97.2 J27.7 R125.1 | length 2363.1
  Top Layer w6: J27.7@115.63,2110.19 124.51,2119.07 cw(c134,2109.58) 134,2123 cw(c134,2106.1) 141.89,2121.05 142.96,2120.43 158.54,2111.46 ccw(c177.52,2144.42) 169.48,2107.25 ccw(c177.52,2144.42) 187.85,2107.82 ccw(c177.52,2144.42) 191.95,2109.23 ccw(c177.52,2144.42) 194.5,2110.38 199.16,2112.7 cw(c201.84,2107.34) 201.84,2113.34 234.62,2113.34 234.96,2113.34 ccw(c234.24,2249.72) 250.9,2114.36 ccw(c238.48,2215.27) 310.38,2143.38 395.43,2228.43 cw(c466.14,2157.72) 466.14,2257.72 613.69,2257.72 cw(c613.69,2250.87) v1(620.54,2250.87) ; v1@620.54,2257.72 635.86,2257.72 cw(c637.26,2245.96) 637.26,2257.8 647.2,2257.8 647.29,2257.72 656.34,2257.72 cw(c656.34,2248.61) 662.78,2255.05 cw(c660.74,2253.01) 663.63,2253.01 ccw(c666.52,2253.01) 664.47,2250.97 669.66,2245.78 ccw(c676.38,2252.51) R125.1@676.38,2243
  Bottom Layer w6: v1(620.54,2250.87) cw(c627.48,2250.87) 627.48,2257.8 639.26,2257.8 ccw(c639.26,2336.54) 718,2336.54 718,2344 cw(c818,2344) 818,2444 1701,2444 cw(c1701,2355) 1790,2355 ccw(c1877.89,2355) 1803,2309 ccw(c1877.89,2355) 1877.89,2267.11 2114.48,2267.11 cw(c2114.48,2252.61) 2128.98,2252.61
TD_A_RJ_P: C95.2 J27.8 R128.1 | length 2378.9
  Top Layer w6: J27.8@177.52,2144.42 177.52,2181.22 cw(c189.43,2181.22) 189.43,2193.14 cw(c189.43,2164.04) 218.53,2164.04 218.53,2143.47 ccw(c229.76,2143.47) 229.76,2132.24 248.81,2132.24 ccw(c238.48,2215.27) 275.5,2140.23 ccw(c238.39,2215.5) 297.69,2156.14 382.74,2241.19 cw(c466.09,2157.83) 466.09,2275.72 613.52,2275.72 ccw(c613.52,2282.74) v1(620.54,2282.74) cw(c620.54,2270.98) v1@628.86,2279.3 ; v1@628.88,2279.27 ccw(c637.26,2287.65) 637.26,2275.8 654.66,2275.8 654.74,2275.72 657.23,2275.72 ccw(c657.23,2281.72) 661.47,2277.48 662.32,2278.33 ccw(c660.14,2280.52) 663.23,2280.52 cw(c666.32,2280.52) 664.13,2282.7 669.26,2287.82 cw(c675.98,2281.1) R128.1@675.98,2290.61
  Bottom Layer w6: v1(620.54,2282.74) ccw(c627.48,2282.74) 627.48,2275.8 635.65,2275.8 ccw(c635.65,2340.15) 700,2340.15 700,2344 cw(c818,2344) 818,2462 1701,2462 cw(c1701,2355) 1808,2355 ccw(c1877.89,2355) 1817.31,2320.14 ccw(c1877.89,2355) 1877.89,2285.11 2114.48,2285.11 ccw(c2114.48,2299.61) 2128.98,2299.61
TD_A_x_N: R122.1 T1.11 U12.2 U12.9 | length 1173.3
  Top Layer w6: T1.11@1419.86,2241.7 cw(c1436.16,2241.7) 1436.16,2258 1495.06,2258 cw(c1495.06,2205.03) 1532.51,2242.49 1549.96,2225.04 ccw(c1606.3,2281.38) 1606.3,2201.7 2534.06,2201.7 cw(c2534.06,2160.73) R122.1@2563.03,2189.7
TD_A_x_P: R119.1 T1.12 U12.1 U12.10 | length 1173.4
  Top Layer w6: T1.12@1419.86,2291.7 ccw(c1435.56,2291.7) 1435.56,2276 1502.52,2276 cw(c1502.52,2223.03) 1539.96,2260.49 1560.44,2240.02 ccw(c1609.49,2289.06) 1609.49,2219.7 2534.06,2219.7 ccw(c2534.06,2260.67) R119.1@2563.03,2231.7
TD_B_cap_N: C101.1 R133.1 | length 413
  Bottom Layer w6: 2171.64,2102.61 ccw(c2171.64,2112.11) 2178.36,2105.39 2183.39,2110.42 ccw(c2180.97,2112.83) 2184.39,2112.83 cw(c2187.8,2112.83) 2185.39,2115.24 cw(c2191.46,2109.17) 2187.17,2116.61 cw(c2191.46,2109.17) 2191.46,2117.76 2322.17,2117.76 cw(c2322.17,2066.02) 2358.76,2102.61 2358.81,2102.56 ccw(c2404.33,2148.08) 2404.33,2083.7 2533.28,2083.7 ; 2534.03,2083.7 cw(c2534.03,2042.73) R133.1@2561.96,2072.7 ; R133.1@2559.84,2072.7 R133.1@2561.96,2072.7 ; R133.1@2563,2071.7 ccw(c2534.03,2042.73) R133.1@2561.96,2072.7 ; R133.1@2563.03,2072.7 R133.1@2561.96,2072.7
TD_B_cap_P: C99.1 R129.1 | length 412.9
  Bottom Layer w6: 2171.81,2150.98 cw(c2171.81,2141.48) 2178.53,2148.2 2183.53,2143.2 cw(c2181.06,2140.72) 2184.56,2140.72 ccw(c2188.06,2140.72) 2185.58,2138.25 ccw(c2191.59,2144.26) 2191.59,2135.76 2322.25,2135.76 cw(c2322.25,2066.21) 2371.43,2115.39 2371.49,2115.33 ccw(c2404.4,2148.25) 2404.4,2101.7 2533.28,2101.7 ; 2534.03,2101.7 ccw(c2534.03,2142.67) R129.1@2561.96,2112.7 ; R129.1@2559.84,2112.7 R129.1@2561.96,2112.7 ; R129.1@2563,2113.7 cw(c2534.03,2142.67) R129.1@2561.96,2112.7 ; R129.1@2563.03,2112.7 R129.1@2561.96,2112.7
TD_B_mag_N: R118.2 T1.17 | length 123.6
  Top Layer w6: R118.2@731.34,2094.78 R118.2@740.18,2103.62 ; R118.2@740.19,2103.63 cw(c750.02,2093.78) 750.02,2107.7 801.68,2107.7 cw(c801.68,2095.7) 810.16,2104.19 810.16,2103.66 816.14,2097.68 ccw(c830.58,2112.12) 830.58,2091.7 T1.17@844.66,2091.7
TD_B_mag_P: R121.2 T1.16 | length 153.8
  Top Layer w6: R121.2@724.43,2138.61 R121.2@728.37,2134.67 ; T1.16@844.66,2141.7 830.58,2141.7 ccw(c830.58,2121.28) 816.14,2135.72 810.16,2129.74 810.16,2129.21 cw(c801.68,2137.7) 801.68,2125.7 750.02,2125.7 ; R121.2@728.37,2134.67 ccw(c750.02,2156.32) 750.02,2125.7 ; R121.2@728.37,2134.67 ccw(c750.02,2156.32) 728.43,2134.61 ccw(c750.02,2156.32) 750.02,2125.7
TD_B_N: R131.2 R133.2 U5.6 | length 1004
  Top Layer w6: R131.2@2610.28,2072.7 2612.19,2072.7 cw(c2640.29,2044.57) 2640.29,2084.33 2642,2084.33 cw(c2642,2062.07) v3@2656.94,2078.57 ; v3(2655.83,2077.52) cw(c2672.92,2060.43) v3@2656.94,2078.57 ; U5.6@3547.71,2052.44 ccw(c3545.67,2050.41) 3545.67,2053.28 3218.39,2053.28 cw(c3218.39,2117.09) 3173.27,2071.97 ccw(c3142.77,2041.47) 3142.77,2084.61 2672.92,2084.61 ccw(c2672.92,2060.43) v3@2656.94,2078.57
  Bottom Layer w6: R133.2@2610.28,2072.54 cw(c2638.38,2044.41) 2638.38,2084.17 2640.09,2084.17 cw(c2640.09,2061.91) v3@2655.83,2077.65
TD_B_P: R127.2 R129.2 U5.5 | length 1001.7
  Top Layer w6: R127.2@2612.19,2114.67 ccw(c2640.29,2142.81) 2640.29,2103.04 2642,2103.04 ccw(c2642,2125.3) v3@2656.69,2108.58 ; v3(2655.83,2109.4) ccw(c2672.23,2125.8) v3@2656.69,2108.58 ; U5.5@3547.71,2072.12 cw(c3545.67,2074.16) 3545.67,2071.28 3218.39,2071.28 cw(c3218.39,2117.09) 3186,2084.7 ccw(c3142.77,2041.47) 3142.77,2102.61 2672.23,2102.61 cw(c2672.23,2125.8) v3@2656.69,2108.58
  Bottom Layer w6: R129.2@2610.28,2114.51 ccw(c2638.38,2142.64) 2638.38,2102.88 2640.09,2102.88 ccw(c2640.09,2125.14) v3(2655.83,2109.4)
TD_B_RJ_N: C101.2 J27.4 R118.1 | length 2392.8
  Top Layer w6: J27.4@177.52,1983.79 200,1961.31 ccw(c208,1969.31) 208,1958 ccw(c208,1976.38) 221,1963.38 ccw(c209.63,1974.75) 225.7,1974.75 225.7,1977.07 ccw(c203.7,1977.07) 219.26,1992.63 cw(c228.66,2002.04) 215.36,2002.04 cw(c227.16,2002.04) 218.82,2010.37 ; 218.85,2010.41 cw(c227.68,2001.51) 227.68,2014.04 432.22,2014.04 ccw(c432.22,2131.91) 515.57,2048.57 544.01,2077.01 cw(c614.72,2006.3) 614.72,2106.3 616.25,2106.3 cw(c616.25,2094.38) 624.68,2102.81 ccw(c633,2111.13) v1(633,2099.37) ccw(c633,2111.13) v1@641.32,2102.81 ; v1@641.34,2102.83 cw(c649.71,2094.46) 649.71,2106.3 657.02,2106.3 cw(c657.02,2096.51) 663.94,2103.43 cw(c662.29,2101.78) 664.63,2101.78 ccw(c666.97,2101.78) 665.32,2100.13 670.66,2094.78 ccw(c677.38,2101.51) R118.1@677.38,2092
  Bottom Layer w6: v1(633,2099.37) cw(c639.94,2099.37) 639.94,2106.3 646.42,2106.3 ccw(c646.42,2139.73) 670.06,2116.09 730.47,2176.51 ccw(c647.11,2259.87) 765,2259.87 765,2302 cw(c857,2302) 857,2394 1542.58,2394 cw(c1542.58,2294) 1613.29,2364.71 1825.67,2152.33 ccw(c1909.05,2235.71) 1908.9,2117.79 ccw(c1909.05,2235.71) 1909.05,2117.79 2089.29,2117.79 2089.33,2117.83 2104.61,2117.83 cw(c2104.61,2109.33) 2110.62,2115.34 cw(c2108.15,2112.87) 2111.65,2112.87 ccw(c2115.15,2112.87) 2112.67,2110.4 2117.67,2105.39 ; 2117.7,2105.36 ccw(c2124.39,2112.11) 2124.35,2102.61
TD_B_RJ_P: C99.2 J27.5 R121.1 | length 2396.8
  Top Layer w6: J27.5@107.44,2023.95 178.66,2026.09 ccw(c177.52,2064.11) 183.49,2026.54 198.38,2028.9 198.92,2028.98 214.06,2031.38 cw(c222.49,1978.51) 222.49,2032.04 432.17,2032.04 ccw(c432.17,2132.04) 502.88,2061.33 532.83,2091.28 cw(c612.55,2011.56) 612.55,2124.3 616.25,2124.3 ccw(c616.25,2136.23) 624.68,2127.8 cw(c633,2119.48) v1(633,2131.24) cw(c633,2119.48) v1@641.32,2127.8 ; v1@641.34,2127.77 ccw(c649.71,2136.15) 649.71,2124.3 656.94,2124.3 ccw(c656.94,2133.92) 663.74,2127.12 ccw(c662.05,2128.81) 664.44,2128.81 cw(c666.83,2128.81) 665.14,2130.49 670.47,2135.82 cw(c677.19,2129.1) R121.1@677.19,2138.61
  Bottom Layer w6: v1(633,2131.24) ccw(c639.94,2131.24) 639.94,2124.3 646.37,2124.3 ccw(c646.37,2139.84) 657.36,2128.85 717.71,2189.2 ccw(c647,2259.91) 747,2259.91 747,2302 cw(c857,2302) 857,2412 1542.61,2412 cw(c1542.61,2294.08) 1625.99,2377.46 1838.37,2165.08 ccw(c1909.08,2235.79) 1909.08,2135.79 2081.84,2135.79 2081.87,2135.83 2104.75,2135.83 ccw(c2104.75,2144.42) 2110.81,2138.33 ; 2110.84,2138.37 ccw(c2108.41,2140.76) 2111.82,2140.73 ; 2111.82,2140.79 cw(c2115.23,2140.76) 2112.8,2143.15 2117.85,2148.2 cw(c2124.57,2141.48) 2124.57,2150.98
TD_B_x_N: R131.1 T1.8 U12.5 U12.6 | length 1179.7
  Top Layer w6: T1.8@1419.86,2091.7 1433.94,2091.7 ccw(c1433.94,2112.12) 1448.38,2097.68 1454.36,2103.66 1454.36,2104.19 cw(c1462.84,2095.7) 1462.84,2107.7 1521.42,2107.7 ccw(c1521.42,2195.32) 1583.33,2133.32 ccw(c1521.42,2195.32) 1583.38,2133.36 cw(c1608.54,2108.2) 1608.54,2143.79 1623.28,2143.79 U12.5@1624.13,2142.94 cw(c1626.16,2140.91) 1626.16,2143.79 1657.61,2143.79 cw(c1657.61,2142.44) 1658.56,2143.39 ccw(c1659.51,2144.34) 1659.51,2143 1711,2143 cw(c1711,2107.26) 1736.27,2132.53 1761.1,2107.7 ccw(c1816.86,2163.46) 1816.86,2084.61 2532.38,2084.61 cw(c2532.38,2043.96) R131.1@2561.12,2072.7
